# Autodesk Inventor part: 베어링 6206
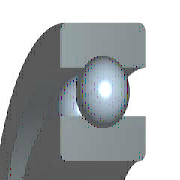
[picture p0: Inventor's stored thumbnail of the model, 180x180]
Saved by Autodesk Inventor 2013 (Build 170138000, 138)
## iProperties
Created: 2009-02
Part Number: 베어링 6206
Material: 강철, 연강
Document SubType Name: Modeling
Standard: KS B 2023
Designer: mdu
Standards Organization: KS
Language: ko-KR
Size Designation: 6206 - 30 x 62 x 16
Categories: <MemberInstance><Categories><Category DisplayName="샤프트 부품" InternalName="7f7aeb1f-a693-4053-b835-cee3144e0d98" Mnemonic="SHFT"><Category DisplayName="베어링" Inter
Density: 1 g/cm^3
IsCustomPart: 0
Author: mdu
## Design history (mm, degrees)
sketch "스케치" dims "d0" = 8.32 (= -0.26 x WD + 0.26 x BD)
  geometry: L1 (3.84, 23)-(12.16, 23); L2 (8, 23)-(8, 18.84); L3 (8, 23)-(8, 27.16); L4 (4.909, 20.216)-(0, 20.216); L5 (0, 15)-(16, 15); L6 (4.909, 25.784)-(0, 25.784); L7 (0, 31)-(16, 31); L8 (16, 15)-(16, 20.216); L9 (11.091, 20.216)-(16, 20.216); L10 (11.091, 25.784)-(16, 25.784); L11 (16, 31)-(16, 25.784); L12 (-1.4, 0)-(8.4, 0) reference; L13 (0, -0.3)-(0, 5.3) reference
  constraints: 22 end point, 4 point on line, 2 collinear, 2 perpendicular, 2 symmetric about line, 1 midpoint, 1 parallel, 14 other
  dimensions: "d9" = 30 diameter of L5 L12 (= WD); "d11" = 62 diameter of L7 L12 (= BD); "d12" = 16 distance between parallel lines of L8 L13 (= KB); "d13" = 40.432 diameter of L9 L12 (= 0.326 x BD + 0.674 x WD)
revolve "본체" stored, may be unused: angle "d6" = 90 deg
revolve "볼" stored, may be unused: angle "d7" = 90 deg
pattern_circular "IDS_ARRAYBALL[SIMPL:T]" dims angle "d3" = 360 deg
body "Solid1"
fillet "모깎기1" dims "d1" = 1 (= KRS)
other parameters: "WD" = 30 [user parameter; used in 5 equation terms], "BD" = 62 [user parameter; used in 5 equation terms], "KB" = 16 [user parameter; used in 1 equation term], "KRS" = 1 [user parameter; used in 1 equation term], "d4" = 0, "d5" = 0, "d8" = 0, "d14" = 0, "d15" = 0, "BBA" = 0 [user parameter], "BC0" = 1.12e+07 [user parameter], "BC" = 1.95e+07 [user parameter], "BR" = 31 (= 0.5 x BD) [user parameter], "WR" = 15 (= 0.5 x WD) [user parameter]
